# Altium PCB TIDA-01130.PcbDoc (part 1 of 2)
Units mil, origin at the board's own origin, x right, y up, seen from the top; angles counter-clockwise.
Board outline 1055.12 x 1877.5 mil, 6 copper layers (Layer 1 - Top Layer, Layer 2 - GND, Layer 3 - Signal, Layer 4 - Signal, Layer 5 - PWR, Layer 6 - Bottom Layer), stack 66.234 mil thick; 91 components, 54 nets, 295 pads, 113 vias.
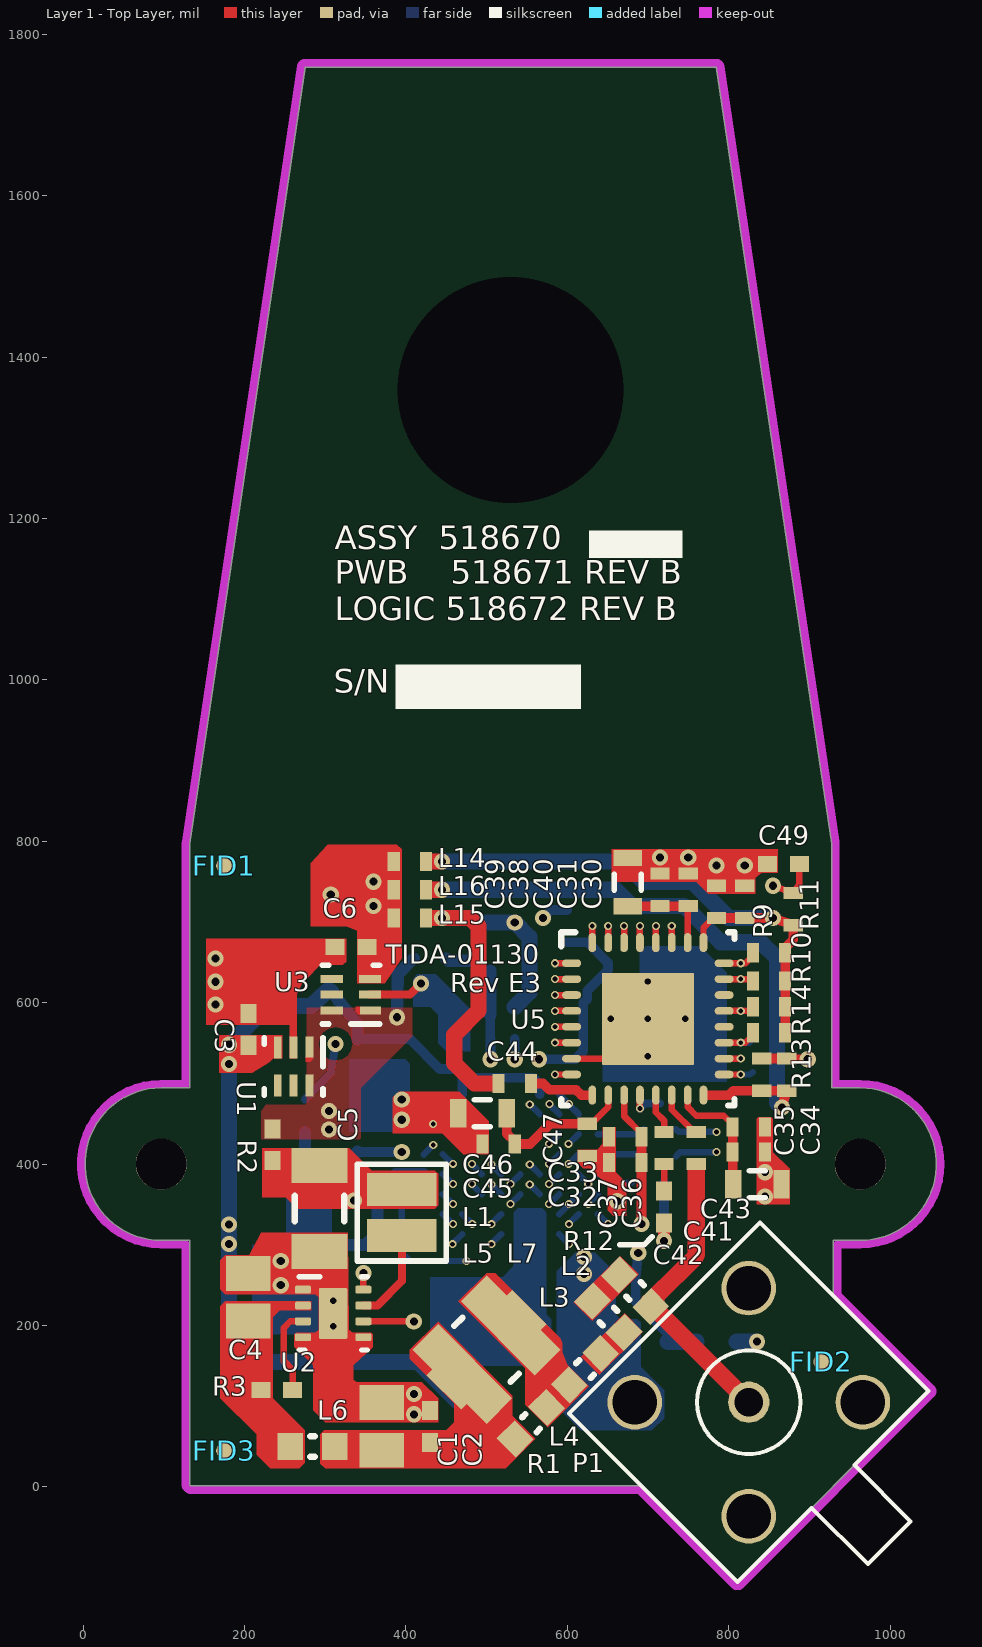
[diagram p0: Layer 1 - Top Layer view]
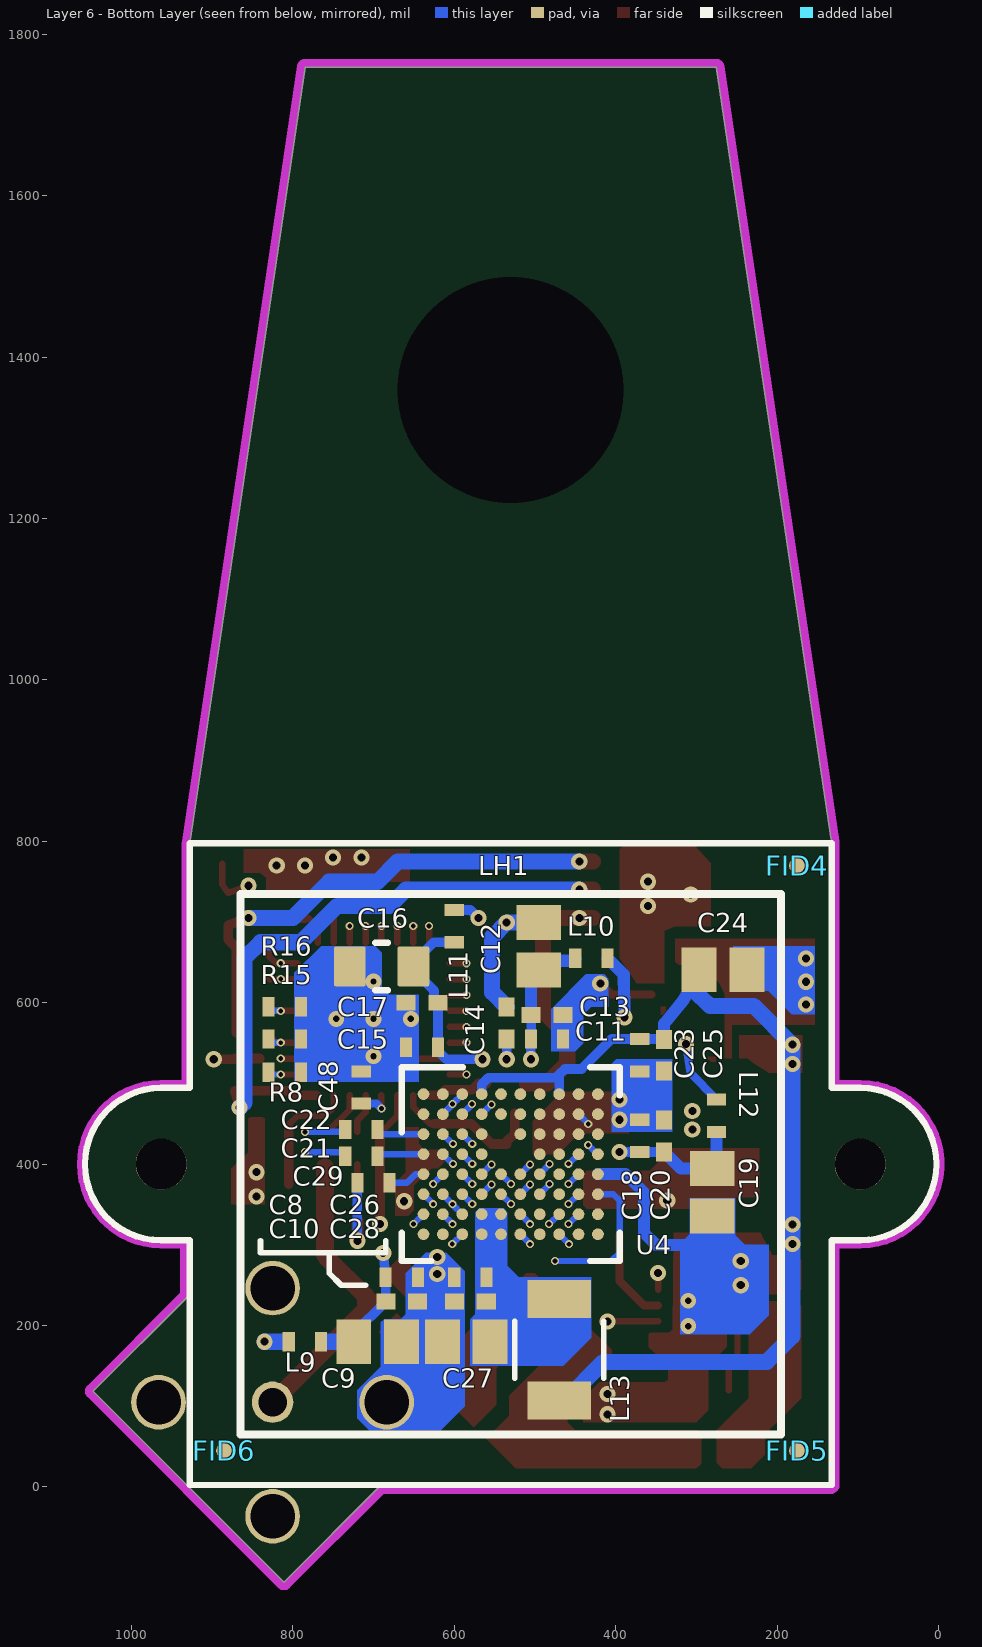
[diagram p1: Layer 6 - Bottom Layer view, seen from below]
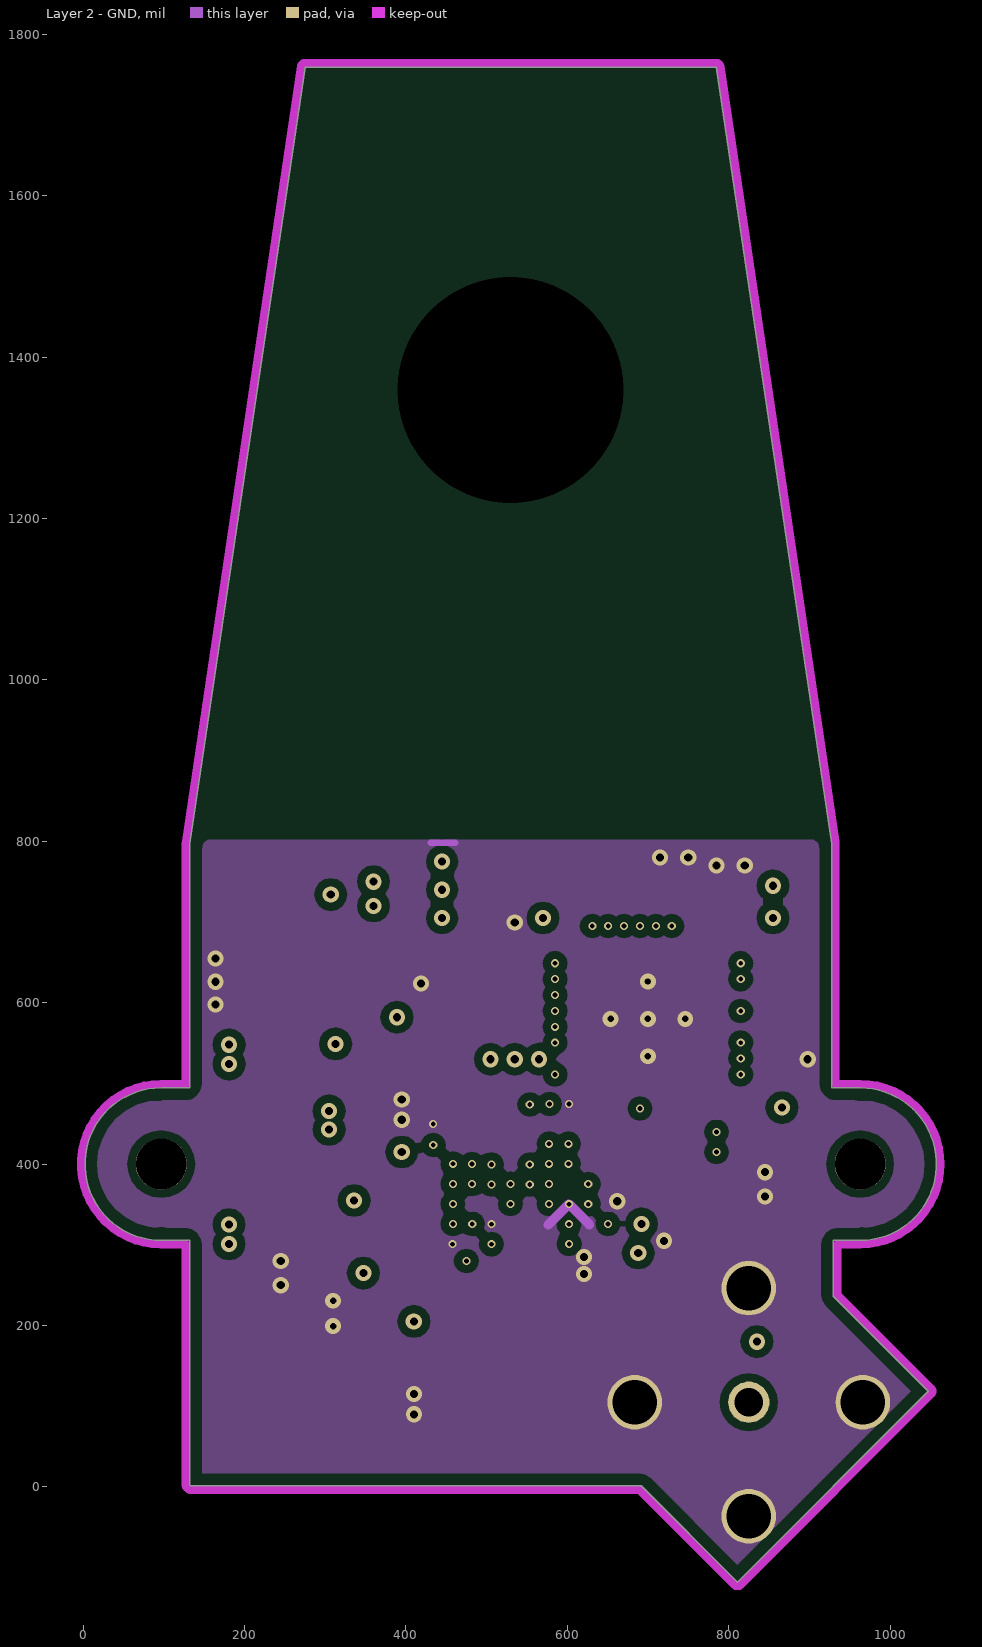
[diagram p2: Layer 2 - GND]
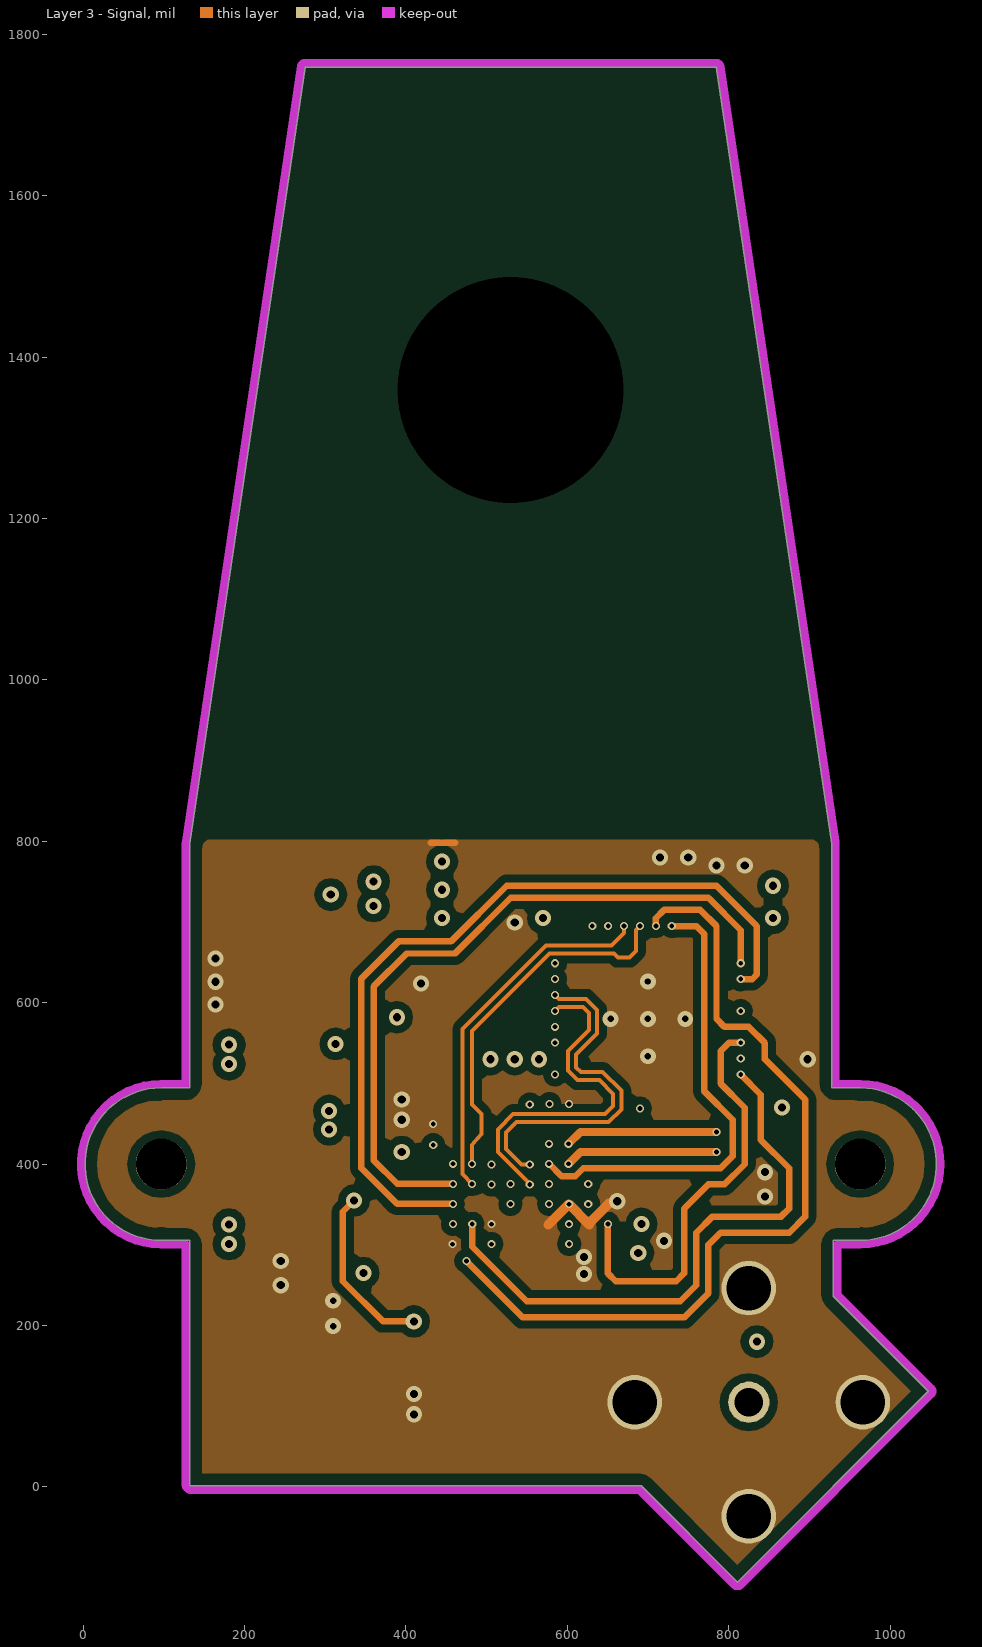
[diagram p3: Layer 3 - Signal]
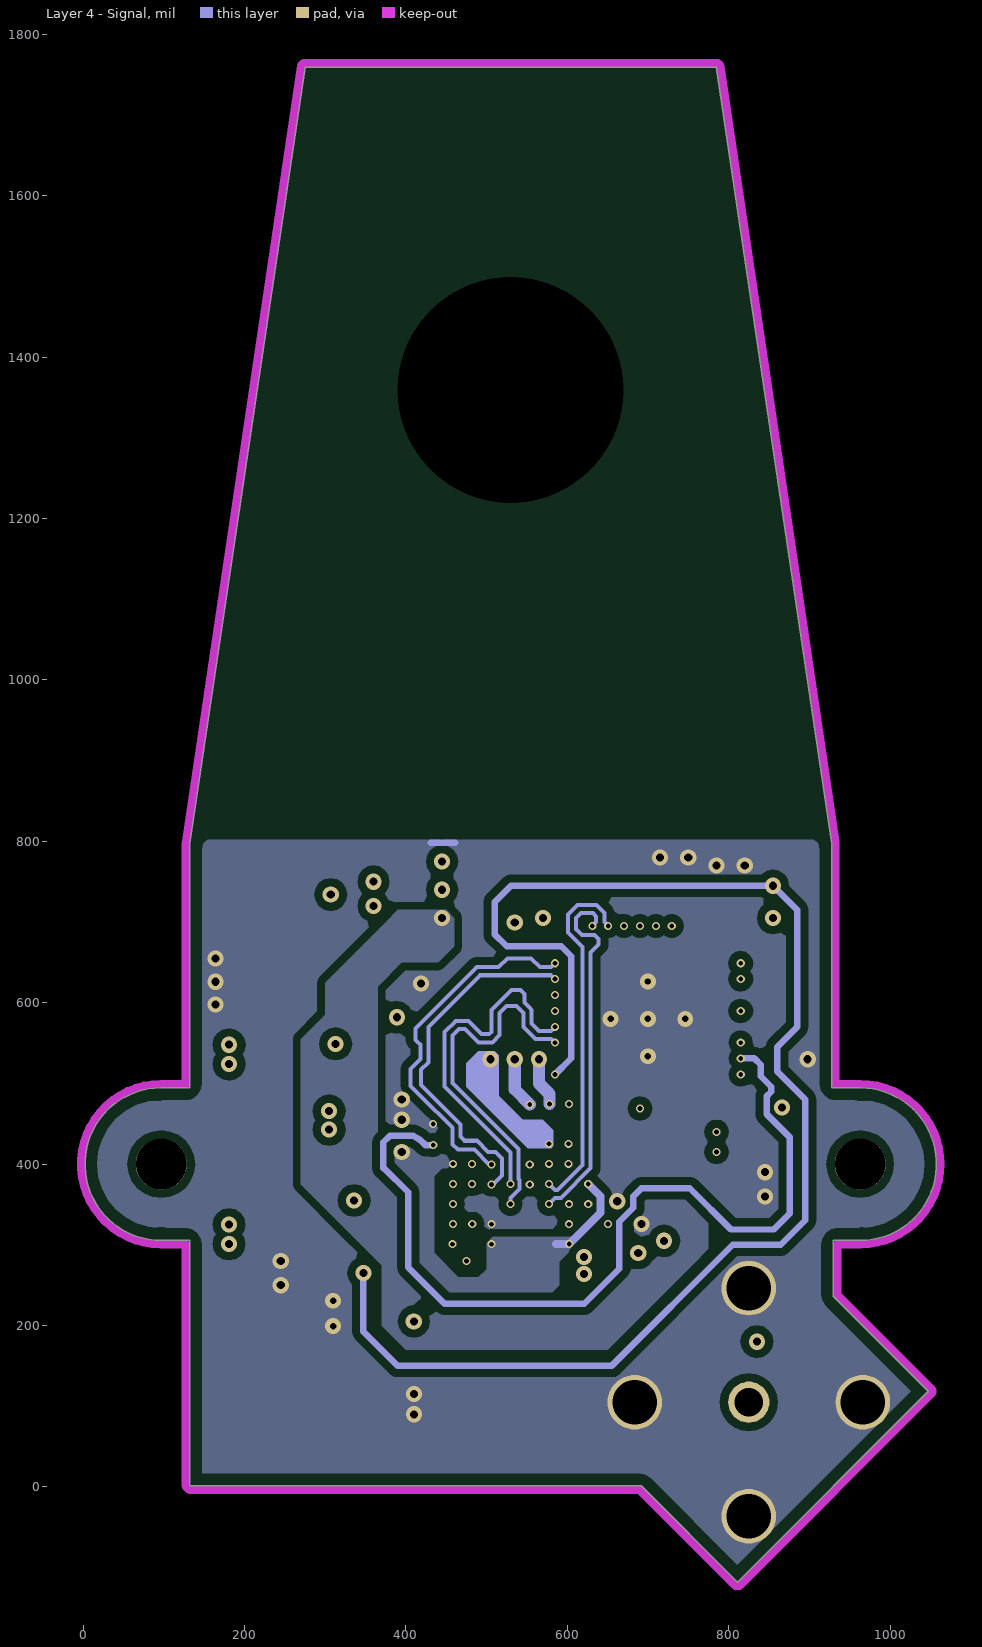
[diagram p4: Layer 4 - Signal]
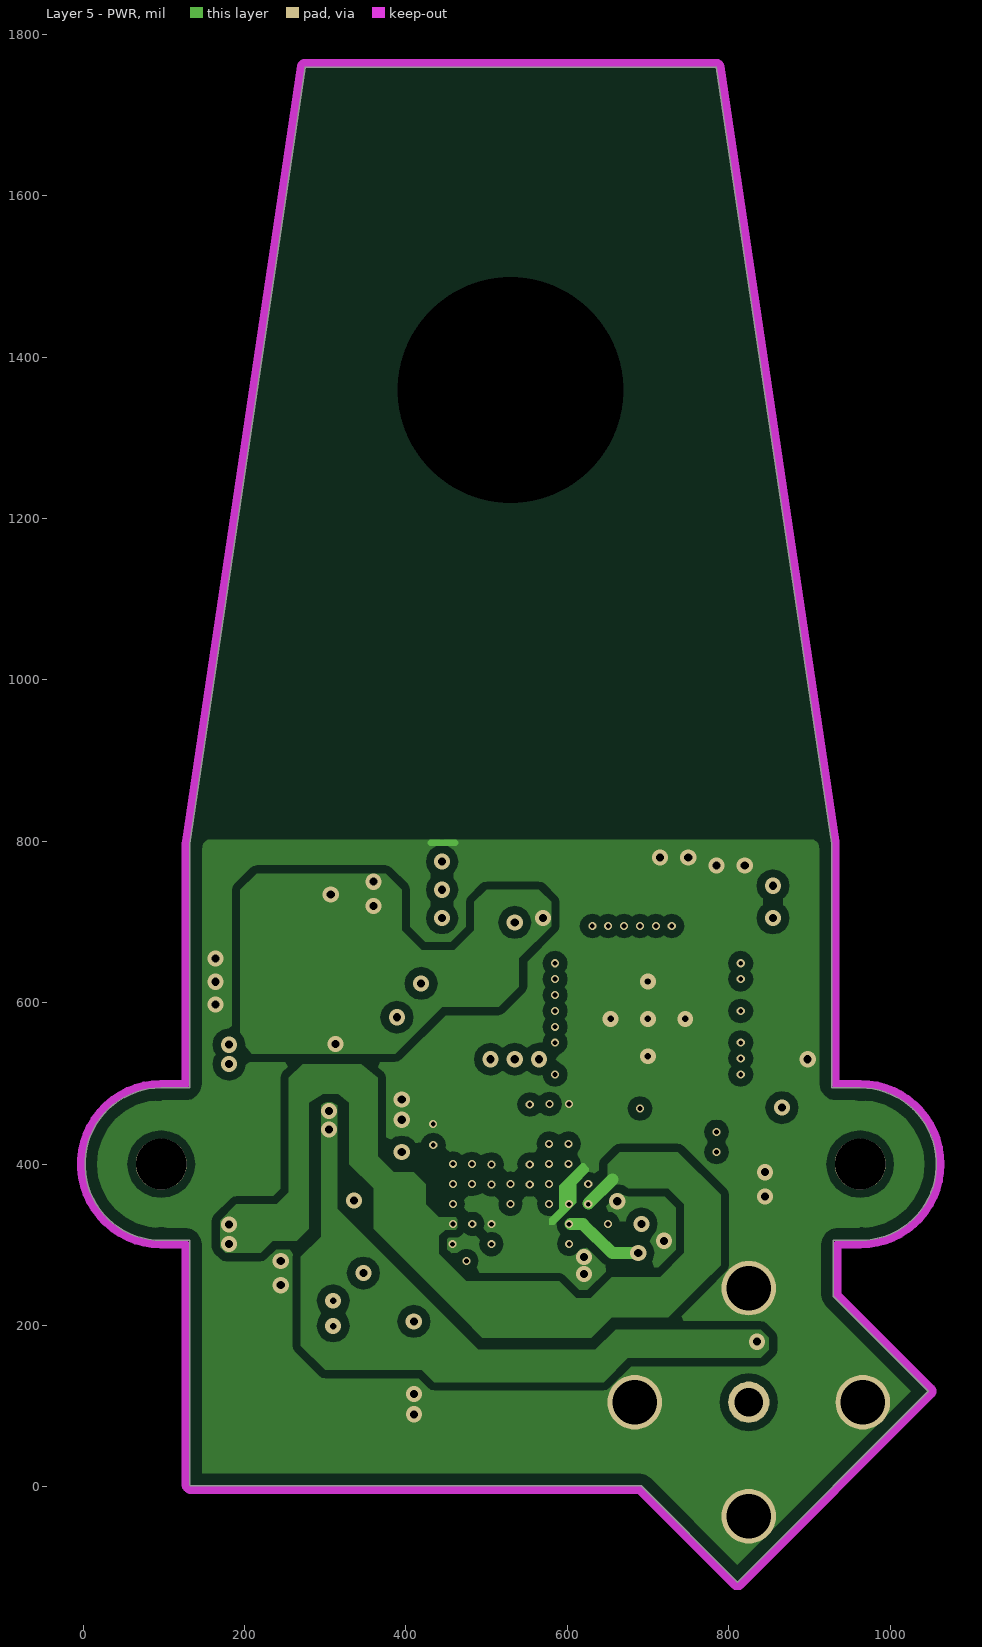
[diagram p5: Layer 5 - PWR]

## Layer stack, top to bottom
Top Solder: solder mask 0.4, Solder Resist, Dk 3.5
Layer 1 - Top Layer: signal copper 1.4
Dielectric 1: prepreg 12.6, 370HR, Dk 4.2
Layer 2 - GND: signal copper 1.4
Dielectric 2: core 8, 370HR, Dk 4.2
Layer 3 - Signal: signal copper 1.417
Dielectric 3: prepreg 16.6, 370HR, Dk 4.2
Layer 4 - Signal: signal copper 1.417
Dielectric 4: core 8, 370HR, Dk 4.2
Layer 5 - PWR: signal copper 1.4
Dielectric 5: prepreg 12.6, 370HR, Dk 4.2
Layer 6 - Bottom Layer: signal copper 1.4
Bottom Solder: solder mask 0.4, Solder Resist, Dk 3.5

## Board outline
96.93,305.51 132.36,305.51 132.36,2.36 133.35,1.37 691.63,1.37 811,-118 1047.5,118.5 929.63,236.37 929.63,305.51 963.07,305.51 ccw(c963.07,400) 963.07,494.49 927.64,494.49 927.64,797.64 927.64,797 784.75,1759.5 275.25,1759.5 132.36,797 132.36,797.64 132.36,494.49 96.93,494.49 ccw(c96.93,400)

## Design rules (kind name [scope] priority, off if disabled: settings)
AcuteAngle [All] p1 off: minimum=4.50000000000000E+0001 checktracksonly=FALSE
AssemblyTestPointUsage [All] p1: valid=2
Clearance Clearance_BoardEdge_MountingHoles [OnCopper and InComponentClass('Mounting Holes') vs IsKeepOut] p1 off: gap=30 ignorepadtopadclearanceinfootprint=FALSE except(0: Arc-Hole Track-Hole SMDPad-Hole THPad-Hole Via-Hole Fill-Hole Poly-Hole Region-Hole Text-Hole)
Clearance Clearance_BoardEdge_Poly [OnCopper and InPoly vs IsKeepOut] p2: gap=15 ignorepadtopadclearanceinfootprint=FALSE except(0: Arc-Hole Track-Hole SMDPad-Hole THPad-Hole Via-Hole Fill-Hole Poly-Hole Region-Hole Text-Hole)
Clearance Clearance_BoardEdge [OnCopper and Not InComponentClass('Logo') and not InComponentClass('FiducialMark') and not InRegion(1000,500,4000,800) and Not IsKeepout vs IsKeepOut and Not OnLayer('Keep-out Layer')] p3: gap=11 ignorepadtopadclearanceinfootprint=FALSE except(0: Arc-Hole Track-Hole SMDPad-Hole THPad-Hole Via-Hole Fill-Hole Poly-Hole Region-Hole Text-Hole)
Clearance Clearance_Poly [InPolygon] p4: gap=10 ignorepadtopadclearanceinfootprint=FALSE except(0: Arc-Hole Track-Hole SMDPad-Hole THPad-Hole Via-Hole Fill-Hole Poly-Hole Region-Hole Text-Hole)
Clearance [All] p5: gap=4 ignorepadtopadclearanceinfootprint=FALSE except(0: Arc-Hole Track-Hole SMDPad-Hole THPad-Hole Via-Hole Fill-Hole Poly-Hole Region-Hole Text-Hole)
ComponentClearance ComponentClearance_1 [issmtcomponent] p1: gap=0 collisioncheckmode=3 verticalgap=0 showdistances=FALSE
ComponentClearance ComponentClearance_Shunt [InComponentClass('Header') vs InComponentClass('Shunt')] p2: gap=0 collisioncheckmode=3 verticalgap=0 showdistances=FALSE
ComponentClearance ComponentClearance_Logo [InComponentClass('Logo')] p3: gap=0 collisioncheckmode=3 verticalgap=0 showdistances=FALSE
ComponentClearance ComponentClearance_ScrewToNut [(HasFootprint('NY PMS 440 0025 PH')) vs (HasFootprint('Keystone_1902C'))] p4: gap=5 collisioncheckmode=3 verticalgap=10 showdistances=FALSE
ComponentClearance ComponentClearance_MountingHoles [InComponentClass('Mounting Holes')] p5: gap=50 collisioncheckmode=3 verticalgap=50 showdistances=FALSE
ComponentClearance ComponentClearance_SmallPassives [HasFootprint('0201*') or HasFootprint('0402*') or HasFootprint('0508') or HasFootprint('0603*') or HasFootprint('0612') or HasFootprint('0805*') or HasFootprint('0815*') or HasFootprint('0830*') or HasFootprint('1206*') or HasFootprint('1210*') or HasFootprint('1808*') or HasFootprint('1812*') or HasFootprint('1825*') or HasFootprint('2010*') or HasFootprint('2220*') or HasFootprint('2225*') or HasFootprint('2512*') or HasFootprint('2728*') or HasFootprint('3518*') vs HasFootprint('0201*') or HasFootprint('0402*') or HasFootprint('0508') or HasFootprint('0603*') or HasFootprint('0612') or HasFootprint('0805*') or HasFootprint('0815*') or HasFootprint('0830*') or HasFootprint('1206*') or HasFootprint('1210*') or HasFootprint('1808*') or HasFootprint('1812*') or HasFootprint('1825*') or HasFootprint('2010*') or HasFootprint('2220*') or HasFootprint('2225*') or HasFootprint('2512*') or HasFootprint('2728*') or HasFootprint('3518*')] p6: gap=0 collisioncheckmode=3 verticalgap=0 showdistances=FALSE
ComponentClearance ComponentClearance_THtoSMT [IsThruComponent vs IsSMTComponent] p7: gap=0 collisioncheckmode=3 verticalgap=0 showdistances=FALSE
ComponentClearance ComponentClearance_THtoTH [IsThruComponent vs IsThruComponent] p8: gap=0 collisioncheckmode=3 verticalgap=0 showdistances=FALSE
ComponentClearance [All] p9: gap=0 collisioncheckmode=3 verticalgap=0 showdistances=FALSE
DiffPairsRouting DiffPair_Diff100_DiffPairsRouting [InDifferentialPairClass('Diff100')] p1: maxlimit=8 minlimit=5 mostfreqgap=8 toplayer_mingap=8 toplayer_minwidth=8 toplayer_maxwidth=8 toplayer_prefwidth=8 midlayer1_mingap=8 midlayer1_minwidth=8 midlayer1_maxwidth=8 midlayer1_prefwidth=8 midlayer2_mingap=8 midlayer2_minwidth=8 midlayer2_maxwidth=8 midlayer2_prefwidth=8 midlayer3_maxgap=5 midlayer3_prefgap=5 midlayer3_minwidth=5 midlayer3_maxwidth=5 midlayer3_prefwidth=5 midlayer4_maxgap=5 midlayer4_prefgap=5 midlayer4_minwidth=5 midlayer4_maxwidth=5 midlayer4_prefwidth=5 bottomlayer_mingap=8 bottomlayer_minwidth=8 bottomlayer_maxwidth=8 bottomlayer_prefwidth=8 maxuncoupledlength=500
DiffPairsRouting [All] p2: maxlimit=5 minlimit=5 mostfreqgap=5 toplayer_minwidth=5 toplayer_maxwidth=15 toplayer_prefwidth=8 midlayer1_minwidth=5 midlayer1_maxwidth=15 midlayer1_prefwidth=8 midlayer2_minwidth=5 midlayer2_maxwidth=15 midlayer2_prefwidth=8 midlayer3_minwidth=5 midlayer3_maxwidth=15 midlayer3_prefwidth=8 midlayer4_minwidth=5 midlayer4_maxwidth=15 midlayer4_prefwidth=8 bottomlayer_minwidth=5 bottomlayer_maxwidth=15 bottomlayer_prefwidth=8 maxuncoupledlength=1000
FabricationTestPointUsage TestPointUsage [All] p1: valid=2 allowmultiple=FALSE
FabricationTestpoint Testpoint [All] p1: side=3 testpointundercomponent=TRUE minsize=40 maxsize=100 preferedsize=60 minholesize=0 maxholesize=40 preferedholesize=32 testpointgrid=1 allowsidetop=TRUE allowsidebottom=TRUE usegrid=TRUE gridtolerance=0.01
FanoutControl Fanout_LCC [IsLCC] p1: bgadir=Out bgaviamode=Centered fanoutstyle=Auto fanoutdirection=Alternating viagrid=1 // Fanout_LCC (Default Rule)
FanoutControl Fanout_BGA [IsBGA] p2: bgadir=Out bgaviamode=Centered fanoutstyle=Auto fanoutdirection=Alternating viagrid=1 // Fanout_BGA (Default Rule)
FanoutControl Fanout_Default [All] p4: bgadir=Out bgaviamode=Centered fanoutstyle=Auto fanoutdirection=Alternating viagrid=1 // Fanout_Default (Default Rule)
FanoutControl Fanout_Small [(CompPinCount < 5)] p5: bgadir=Out bgaviamode=Centered fanoutstyle=Auto fanoutdirection=OutThenIn viagrid=1 // Fanout_Small (Default Rule)
HoleSize [All] p1: absolutevalues=TRUE maxlimit=280 minlimit=6 maxpercent=80.000 minpercent=20.000
MatchedLengths DiffPair_Diff100_MatchedLengths [InDifferentialPairClass('Diff100')] p1: tolerance=25 checknetsindiffpair=FALSE checkdiffpairvsdiffpair=TRUE checkxsignals=TRUE checkothers=TRUE
MinimumAnnularRing MinimumAnnularRing_ThermalPadVias [IsVia and InAnyComponent] p1: minimumring=5.91
MinimumAnnularRing [All] p2: minimumring=2
MinimumSolderMaskSliver MinimumSolderMaskSliver_Logo [InComponentClass('Logo') vs InComponentClass('Logo')] p1: minsoldermaskwidth=0.7
MinimumSolderMaskSliver [All] p2: minsoldermaskwidth=3.94
PlaneConnect [All] p1: planeconnectstyle=Relief reliefexpansion=10 reliefentries=4 reliefconductorwidth=10 reliefairgap=10
PolygonConnect [All] p1: connectstyle=Direct reliefconductorwidth=10 reliefentries=4 polygonreliefangle="90 Angle" airgapwidth=10
RoutingVias ThermalPadVias [IsVia and InAnyComponent] p1: holewidth=7.87 width=19.68 viastyle="Through Hole" minholewidth=7.87 minwidth=19.68 maxholewidth=12.99 maxwidth=23.62
RoutingVias [All] p2: holewidth=10 width=22 viastyle="Through Hole" minholewidth=6 minwidth=10 maxholewidth=40 maxwidth=65
SMDToCorner [All] p1: distance=25000
SilkToSilkClearance [All] p1: silktosilkclearance=0
SilkToSolderMaskClearance SilkscreenOverComponentPads [IsPad] p1: minsilkscreentomaskgap=0.2 clearancetoexposedcopper=TRUE
SolderMaskExpansion [All] p1: expansion=1
Width [All] p1: maxlimit=100 minlimit=5 preferedwidth=10 minimp=50.000000 maximp=50.000000 favimp=50.000000 checkconnectedcopper=TRUE
16 further rules are at their usual default settings.

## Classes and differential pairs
differential pair class Diff100: CSI0_CLK CSI0_D0 CSI0_D1 CSI0_D2 CSI0_D3
component class Serializer: C30 C31 C32 C33 C34 C35 C36 C37 C38 C39 C40 C41 C42 C43 C44 C45 C46 C47 C48 C49 L14 L15 L16 R9 R10 R11 R12 R13 R14 R15 R16 U5
component class "Coax Connection and Power Supply": C1 C2 C3 C4 C5 C6 L1 L2 L3 L4 L5 L6 L7 P1 R1 R2 R3 U1 U2 U3
component class Imager: C8 C9 C10 C11 C12 C13 C14 C15 C16 C17 C18 C19 C20 C21 C22 C23 C24 C25 C26 C27 C28 C29 L9 L10 L11 L12 L13 R8 R23 U4
component class AssemblyNote: ZZ1 ZZ2 ZZ3
component class FiducialMark: FID1 FID2 FID3 FID4 FID5 FID6
component class HDWR: FID1 FID2 FID3 FID4 FID5 FID6 LH1 ZZ1 ZZ2 ZZ3
differential pair CSI0_CLK: +CSI0_CLK_P -CSI0_CLK_N
differential pair CSI0_D0: +CSI0_D0_P -CSI0_D0_N
differential pair CSI0_D1: +CSI0_D1_P -CSI0_D1_N
differential pair CSI0_D2: +CSI0_D2_P -CSI0_D2_N
differential pair CSI0_D3: +CSI0_D3_P -CSI0_D3_N

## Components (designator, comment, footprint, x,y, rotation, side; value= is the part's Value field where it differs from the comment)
C1 "CGA4J1X7R1E475M125AC" 0805L 370,75 r90 top value=4.7µF
C2 "C1005X7R1E104K050BB" 0402L 430,75 r90 top value=0.1µF
C3 "CL05B105KQ5NQNC" 0402L 205,567 r90 top value=1.0µF
C4 "CL21B106KOQNNNE" 0805L 204.53,235 r90 top value=10uF
C5 "GRM31CR71A226KE15L" 1206L 293,345 r270 top value=22uF
C6 "CL05B105KQ5NQNC" 0402L 332,669 r180 top value=1.0µF
C8 "0402YC104KAT2A" 0402S 665,260 r180 bottom value=0.1uF
C9 "CL21B106KOQNNNE" 0805L 695,180 r180 bottom value=10uF
C10 "CL05B105KQ5NQNC" 0402L 665,230 r180 bottom value=1.0µF
C11 "0402YC104KAT2A" 0402S 485,555 r180 bottom value=0.1uF
C12 "CL21B106KOQNNNE" 0805L 495,670 r90 bottom value=10uF
C13 "CL05B105KQ5NQNC" 0402L 485,585 r180 bottom value=1.0µF
C14 "JMK105B7474KVHF" 0402L 535,575 r90 bottom value=0.47uF
C15 "0402YC104KAT2A" 0402S 640,545 r0 bottom value=0.1uF
C16 "CL21B106KOQNNNE" 0805_HV1 690,645 r0 bottom value=10uF
C17 "CL05B105KQ5NQNC" 0402L 640,600 r0 bottom value=1.0µF
C18 "0402YC104KAT2A" 0402S 370,435 r90 bottom value=0.1uF
C19 "CL21B106KOQNNNE" 0805L 280,365 r270 bottom value=10uF
C20 "CL05B105KQ5NQNC" 0402L 340,435 r90 bottom value=1.0µF
C21 "GRM155R71H103KA88D" 0402S 715,410 r180 bottom value=0.01uF
C22 "JMK105B7474KVHF" 0402S 715,443 r0 bottom value=0.47uF
C23 "0402YC104KAT2A" 0402S 370,535 r270 bottom value=0.1uF
C24 "CL21B106KOQNNNE" 0805L 267,641 r180 bottom value=10uF
C25 "CL05B105KQ5NQNC" 0402L 340,535 r270 bottom value=1.0µF
C26 "0402YC104KAT2A" 0402S 580,260 r0 bottom value=0.1uF
C27 "CL21B106KOQNNNE" 0805L 585,180 r0 bottom value=10uF
C28 "CL05B105KQ5NQNC" 0402L 580,230 r0 bottom value=1.0µF
C29 "JMK105B7474KVHF" 0402S 700,377 r0 bottom value=0.47uF
C30 "0402YC104KAT2A" 0402S 820,725 r90 top value=0.1uF
C31 "GRM155R71C103KA01D" 0402S 785,725 r90 top value=0.01uF
C32 "0402YC104KAT2A" 0402S 672,402 r180 top value=0.1uF
C33 "GRM155R71C103KA01D" 0402S 672,433.78 r180 top value=0.01uF
C34 "0402YC104KAT2A" 0402S 872,511 r90 top value=0.1uF
C35 "GRM155R71C103KA01D" 0402S 841,511 r90 top value=0.01uF
C36 "CGA2B3X7R1H333K050BB" 0402S 760,420 r90 top value=0.033uF
C37 "CGA2B3X7R1H153K050BB" 0402S 720,420 r90 top value=0.015uF
C38 "0402YC104KAT2A" 0402S 715,740 r90 top value=0.1uF
C39 "JMK107BB7475MA-T" 0603S 675,749.53 r270 top value=4.7uF
C40 "GRM155R71C103KA01D" 0402S 750,740 r90 top value=0.01uF
C41 "0402YC104KAT2A" 0402S 825,415 r0 top value=0.1uF
C42 "JMK107BB7475MA-T" 0603S 835.75,375 r180 top value=4.7uF
C43 "GRM155R71C103KA01D" 0402S 825,446 r0 top value=0.01uF
C44 "GRM155R70J223KA01D" 0402S 535,500 r0 top value=0.022uF
C45 "0402YC104KAT2A" 0402S 515,425 r180 top value=0.1uF
C46 "JMK107BB7475MA-T" 0603S 495,463 r0 top value=4.7uF
C47 "GRM155R71C103KA01D" 0402S 625,430 r270 top value=0.01uF
C48 "0402YC104KAT2A" 0402S 715,495 r90 bottom value=0.1uF
C49 "GRM155R60J474KE19D" 0402L 868,772 r180 top value=0.47uF
FID1 "Fiducial" Fiducial10-20#1 175,770 r0 top
FID2 "Fiducial" Fiducial10-20#2 885,45 r0 top
FID3 "Fiducial" Fiducial10-20#1 175,45 r0 top
FID4 "Fiducial" Fiducial10-20#1 175,770 r90 bottom
FID5 "Fiducial" Fiducial10-20#1 175,45 r90 bottom
FID6 "Fiducial" Fiducial10-20#1 885,45 r90 bottom
L1 "XPL2010-222MLB" XPL2010 395.04,340 r90 top value=2.2uH
L2 "BLM18HE152SN1D" 0603L 684,243 r135 top value="1500 ohm"
L3 "BLM18HE152SN1D" 0603L 651,211 r315 top value="1500 ohm"
L4 "BLM18HE152SN1D" 0603L 622,146 r225 top value="1500 ohm"
L5 "LQH3NPN100NG0" LQH3NP_G0 500,170 r45 top value=10uH
L6 "BLM18AG102SN1D" 0603L 284.57,50 r180 top value="1000 ohm"
L7 "ADL3225V-470M-2P" ADL3225V 500,170 r225 top value=47uH
L9 "BLM15AX102SN1D" 0402S 785,180 r180 bottom value="1000 ohm"
L10 "BLM15AX102SN1D" 0402S 430,655 r0 bottom value="1000 ohm"
L11 "BLM15AX102SN1D" 0402S 600,695 r270 bottom value="1000 ohm"
L12 "BLM15AX102SN1D" 0402S 275,460 r270 bottom value="1000 ohm"
L13 "NLCV32T-R22M-PFR" NLCV32 470,170 r90 bottom value=220nH
L14 "BLM15AX102SN1D" 0402S 405,775 r0 top value="1000 ohm"
L15 "BLM15AX102SN1D" 0402S 405,705 r0 top value="1000 ohm"
L16 "BLM15AX102SN1D" 0402S 405,740 r0 top value="1000 ohm"
LH1 "CMT821" CMT821 530,400 r180 bottom locked
P1 "59S10H-40ML5-Y" 59S10H-40ML5-Y 825,105 r315 top locked
R1 "CRCW06034K02FKEA" 0603L 555,79 r45 top value=4.02k
R2 "CRCW04020000Z0ED" 0402L 235,424 r270 top value=0
R3 "CRCW040210K0JNED" 0402L 240,120 r180 top value=10k
R8 "CRCW040210K0JNED" 0402S 810,514 r0 bottom value=10k
R9 "CRCW04023K30JNED" 0402S 850,662 r0 top value=3.3k
R10 "CRCW04023K30JNED" 0402S 850,627 r0 top value=3.3k
R11 "CRCW040210K0JNED" 0402S 880,716 r270 top value=10k
R12 "CRCW040249R9FKED" 0402L 720,347 r90 top value=49.9
R13 "CRCW040210K0JNED" 0402S 850,563 r0 top value=10k
R14 "CRCW040210K0JNED" 0402S 850,595 r0 top value=10k
R15 "CRCW0402402RFKED" 0402S 810,555 r0 bottom value=402
R16 "CRCW0402402RFKED" 0402S 810,595 r0 bottom value=402
U1 "TLV70213DSERQ1" DSE0006A 261,521 r270 top
U2 "TPS62172QDSGRQ1" DSG0008A 310,215 r0 top
U3 "TLV70218DSERQ1" DSE0006A 332,610 r180 top
U4 "OV02775-E77Y-1A-Z" aCSP-77 530,400 r180 bottom locked
U5 "DS90UB953QRHBQ1" RHB0032B 700,580 r0 top locked
ZZ1 "These assemblies are ESD sensitive, ESD precautions shall be observed." AssemblyNote 200,2100 r0 top
ZZ2 "These assemblies must be clean and free from flux and all contaminants. Use of no clean flux is not acceptable." AssemblyNote 200,2000 r0 top
ZZ3 "These assemblies must comply with workmanship standards IPC-A-610 Class 2, unless otherwise specified." AssemblyNote 200,1900 r0 top

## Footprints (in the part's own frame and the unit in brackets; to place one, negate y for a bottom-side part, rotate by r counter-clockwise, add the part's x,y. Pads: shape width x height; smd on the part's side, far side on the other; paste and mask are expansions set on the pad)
59S10H-40ML5-Y [mm] "Rosenberger Straight Plug"
  round 1.3 hole 0.9 mask+0: 1(0,0)
  round 1.72 hole 1.4 mask+0: 2(-2.54,2.54) 3(-2.54,-2.54) 4(2.54,-2.54) 5(2.54,2.54)
  silkscreen extent -3.75,-4.25 6.25,4.25
0402L [mm] "0402 from SM-752 data"
  rect 0.6x0.5 smd: 1(-0.5,0) 2(0.5,0)
  body extent -0.55,-0.3 0.55,0.3, height 0.6
0402S [mil] "Based on C0402S footprint from PADS legacy"
  rect 15x24 smd: 1(-20,0) 2(20,0)
  body extent -22,-12 22,12, height 24
0603L [mm] "0603 from SM-752 data"
  rect 0.8x0.85 smd: 1(-0.7,0) 2(0.7,0)
  silkscreen extent -0.07,-0.32 0.07,0.32, body extent -0.87,-0.47 0.87,0.47, height 1
0603S [mil]
  rect 20x35 smd: 1(-30,0) 2(30,0)
  silkscreen extent -10,-17 10,17, body extent -34,-19 34,19, height 39
0805_HV1 [mm] "Custom footprint based on analyzing multiple manufacturer recommendations"
  rrect10% 1x1.25 smd: 1(-1,0) 2(1,0)
  silkscreen extent -0.2,-0.75 0.2,0.75, body extent -1.1,-0.72 1.1,0.73, height 1.45
0805L [mm] "0805 from SM-752 data"
  rect 1.1x1.4 smd: 1(-0.75,0) 2(0.75,0)
  body extent -1.1,-0.72 1.1,0.72, height 1.1
1206L [mm] "1206 from SM-752 data"
  rect 1.1x1.75 smd: 1(-1.35,0) 2(1.35,0)
  silkscreen extent -0.4,-0.77 0.4,0.77, body extent -1.7,-0.9 1.7,0.9, height 1.35
aCSP-77 [mm] "BGA, 77-Leads, Body 6.534x5.724mm"
  round 0.37 smd: A1(-2.745,2.205) A2(-2.135,2.205) A3(-1.525,2.205) A4(-0.915,2.205) A5(-0.305,2.205) A6(0.305,2.205) A7(0.915,2.205) A8(1.525,2.205) A9(2.135,2.205) A10(2.745,2.205) B1(-2.745,1.575) B2(-2.135,1.575) B3(-1.525,1.575) B4(-0.915,1.575) B5(-0.305,1.575) B6(0.305,1.575) B7(0.915,1.575) B8(1.525,1.575) B9(2.135,1.575) B10(2.745,1.575) C1(-2.745,0.945) C2(-2.135,0.945) C3(-1.525,0.945) C4(-0.915,0.945) C6(0.305,0.945) C7(0.915,0.945) C8(1.525,0.945) C9(2.135,0.945) C10(2.745,0.945) D1(-2.745,0.315) D2(-2.135,0.315) D3(-1.525,0.315) D4(-0.915,0.315) D7(0.915,0.315) D8(1.525,0.315) D9(2.135,0.315) D10(2.745,0.315) E1(-2.745,-0.315) E2(-2.135,-0.315) E3(-1.525,-0.315) E4(-0.915,-0.315) E5(-0.305,-0.315) E6(0.305,-0.315) E7(0.915,-0.315) E8(1.525,-0.315) E9(2.135,-0.315) E10(2.745,-0.315) F1(-2.745,-0.945) F2(-2.135,-0.945) F3(-1.525,-0.945) F4(-0.915,-0.945) F5(-0.305,-0.945) F6(0.305,-0.945) F7(0.915,-0.945) F8(1.525,-0.945) F9(2.135,-0.945) F10(2.745,-0.945) G1(-2.745,-1.575) G2(-2.135,-1.575) G3(-1.525,-1.575) G4(-0.915,-1.575) G5(-0.305,-1.575) G6(0.305,-1.575) G7(0.915,-1.575) G8(1.525,-1.575) G9(2.135,-1.575) G10(2.745,-1.575) H1(-2.745,-2.205) H2(-2.135,-2.205) H3(-1.525,-2.205) H4(-0.915,-2.205) H5(-0.305,-2.205) H6(0.305,-2.205) H7(0.915,-2.205) H8(1.525,-2.205) H9(2.135,-2.205) H10(2.745,-2.205)
  silkscreen extent -3.43,-3.05 3.43,3.05, body extent -3.28,-2.88 3.28,2.88, height 1.04
ADL3225V [mm] "SMD, 2-Leads, Body 3.2x2.5mm"
  rect 0.9x1.53 smd: 1(-1.45,0) 2(1.45,0)
  silkscreen extent -0.18,-1.25 0.18,1.25, body extent -1.61,-1.25 1.61,1.25, height 2.4
AssemblyNote [mil] "Assembly Note"
CMT821 [mm] "SUNEX Lens Holder"
  round 1.6 hole 1.6 unplated paste+0: MT1(-11,0) MT2(11,0)
  M6 Assembly Bottom keep-out lines w0.2: 8.5,-8.5 8.5,8.5 -8.5,8.5 -8.5,-8.5 8.5,-8.5
  silkscreen extent -13.4,-10.1 13.4,10.1
DSE0006A [mm] "TI recommended land pattern"
  rect 0.66x0.25 smd: 1(-0.62,0.5)
  rect 0.7x0.25 smd: 2(-0.6,0) 3(-0.6,-0.5) 4(0.6,-0.5) 5(0.6,0) 6(0.6,0.5)
  Layer 1 - Top Layer region: -0.3,0.625 -0.25,0.625 -0.15,0.525 -0.15,0.375 -0.3,0.375
  silkscreen extent -0.9,-0.92 0.9,0.92, body extent -0.77,-0.77 0.77,0.77, height 0.8
DSG0008A [mm] "SON, 8-Leads, Body 2x2mm, Pitch 0.5mm, Thermal Pad 1.6x0.9mm, TI Recommended"
  rrect40% 0.5x0.25 smd: 1(-0.95,0.75) 2(-0.95,0.25) 3(-0.95,-0.25) 4(-0.95,-0.75) 5(0.95,-0.75) 6(0.95,-0.25) 7(0.95,0.25) 8(0.95,0.75)
  rrect11% 0.9x1.6 smd paste-0.45: 9(0,0)
  silkscreen extent -1.07,-1.15 1.07,1.15, body extent -1.05,-1.05 1.05,1.05, height 0.8
Fiducial10-20#1 [mil]
  round 20 smd paste-19.68 mask+19.68: 1(0,0)
Fiducial10-20#2 [mil]
  round 20 smd paste-19.68 mask+19.68: 1(30,110)
LQH3NP_G0 [mm] "MURATA"
  rect 1.15x3.3 smd: 1(-1.075,0) 2(1.075,0)
  body extent -1.6,-1.6 1.6,1.6, height 1.01
NLCV32 [mm] "TDK"
  rect 1.2x2 smd: 1(-1.6,0) 2(1.6,0)
  silkscreen extent -0.9,-1.4 0.9,1.4, body extent -1.7,-1.35 1.7,1.35, height 2.4
RHB0032B [mm] "QFN, 32-Leads, Body 5x5mm, Pitch 0.5mm, Thermal Pad 2.9x2.9mm"
  rrect100% 0.6x0.24 smd: 1(-2.4,1.75) 2(-2.4,1.25) 3(-2.4,0.75) 4(-2.4,0.25) 5(-2.4,-0.25) 6(-2.4,-0.75) 7(-2.4,-1.25) 8(-2.4,-1.75) 17(2.4,-1.75) 18(2.4,-1.25) 19(2.4,-0.75) 20(2.4,-0.25) 21(2.4,0.25) 22(2.4,0.75) 23(2.4,1.25) 24(2.4,1.75)
  rrect100% 0.24x0.6 smd: 9(-1.75,-2.4) 10(-1.25,-2.4) 11(-0.75,-2.4) 12(-0.25,-2.4) 13(0.25,-2.4) 14(0.75,-2.4) 15(1.25,-2.4) 16(1.75,-2.4) 25(1.75,2.4) 26(1.25,2.4) 27(0.75,2.4) 28(0.25,2.4) 29(-0.25,2.4) 30(-0.75,2.4) 31(-1.25,2.4) 32(-1.75,2.4)
  rrect3% 2.9x2.9 smd paste-1.725: 33(0,0)
  silkscreen extent -2.72,-2.73 2.72,2.72, body extent -2.57,-2.58 2.58,2.57, height 1.01
XPL2010 [mm] "Coilcraft recommended land pattern Document 646-2 Revised 3/28/11"
  rect 1.04x2.2 smd: 1(-0.725,0) 2(0.725,0)
  silkscreen extent -1.52,-1.4 1.52,1.4, body extent -1.05,-1.1 1.05,1.1, height 1

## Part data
C1: library part C2012X7R1E474K, "CAP, CERM, 4.7uF, 25V, +/-20%, X7R, 0805", Manufacturer="TDK Corporation", Operating Temperature="-55°C ~ 125°C", Ratings=AEC-Q200, Supplier Part Number 1=445-12761-1-ND, TempCo=X7R, Tolerance_%=±20%
C2: library part C1005X7R1E103K, "CAP, CERM, 0.1uF, 25V, +/-10%, X7R, 0402", Manufacturer="TDK Corporation", Operating Temperature="-55°C ~ 125°C", Ratings=-, Supplier Part Number 1=445-7348-1-ND, TempCo=X7R, Tolerance_%=±10%
C3 C6 C10 C13 C17 C20 C25 C28: library part Capacitor, "CAP CER 1UF 6.3V 10% X7R 0402", Alternate Manufacturer=-, Manufacturer="Samsung Electro-Mechanics America, Inc", Operating Temperature="-55°C ~ 125°C", Supplier Part Number 1=1276-1513-1-ND, TempCo=X7R, Tolerance_%=±10%
C4 C9 C12 C16 C19 C24 C27: "CAP, CERM, 10 µF, 16 V, +/- 10%, X7R, 0805", Cap_Case=0805, Manufacturer="Samsung Electro-Mechanics", TempCo=X7R, Tolerance_%=10, Value1=Unknown, Value2=16V, ValueDisplayed=10µF
C5: "CAP, CERM, 22uF, 10V, +/-10%, X7R, 1206", Cap_Case=1206, Manufacturer=MuRata, Supplier Part Number 1=490-5309-1-ND, TempCo=X7R, Tolerance_%=10, Value1=Unknown, Value2=10V, ValueDisplayed=22µF
C8 C11 C15 C18 C23 C26 C30 C32 C34 C38 C41 C45 C48: "CAP, CERM, 0.1 µF, 16 V, +/- 10%, X7R, 0402", Cap_Case=0402, Manufacturer=AVX, Supplier Part Number 1=478-7888-1-ND, TempCo=X7R, Tolerance_%=10, Value1=Unknown, Value2=16V, ValueDisplayed=0.1µF
C14 C22 C29: "CAP, CERM, 0.47 µF, 6.3 V, +/- 10%, X7R, 0402", Cap_Case=0402, Manufacturer="Taiyo Yuden", Supplier Part Number 1=587-3765-1-ND, TempCo=X7R, Tolerance_%=10, Value1=Unknown, Value2=6.3V, ValueDisplayed=0.47µF
C21: "CAP, CERM, 0.01 µF, 50 V, +/- 10%, X7R, 0402", Cap_Case=0402, Manufacturer=MuRata, Supplier Part Number 1=490-4516-1-ND, TempCo=X7R, Tolerance_%=10, Value1=Unknown, Value2=50V, ValueDisplayed=0.01µF
C31 C33 C35 C40 C43 C47: "CAP, CERM, 0.01uF, 16V, +/-10%, X7R, 0402", Cap_Case=0402, Manufacturer=MuRata, Supplier Part Number 1=490-1313-1-ND, TempCo=X7R, Tolerance_%=10, Value1=Unknown, Value2=16V, ValueDisplayed=0.01µF
C36: "CAP, CERM, 0.033 µF, 50 V, +/- 10%, X7R, 0402", Cap_Case=0402, Manufacturer=TDK, Supplier Part Number 1=445-6896-1-ND, TempCo=X7R, Tolerance_%=10, Value1=Unknown, Value2=50V, ValueDisplayed=0.033µF
C37: "CAP, CERM, 0.015 µF, 50 V, +/- 10%, X7R, AEC-Q200 Grade 1, 0402", Cap_Case=0402, Manufacturer=TDK, Supplier Part Number 1=445-6894-1-ND, TempCo=X7R, Tolerance_%=10, Value1="0.2162 ohm", Value2=50V, ValueDisplayed=0.015µF
C39 C42 C46: "CAP, CERM, 4.7 µF, 6.3 V, +/- 10%, X7R, 0603", Cap_Case=0603, Manufacturer="Taiyo Yuden", TempCo=X7R, Tolerance_%=10, Value1=Unknown, Value2=6.3V, ValueDisplayed=4.7µF
C44: "CAP, CERM, 0.022 µF, 6.3 V, +/- 10%, X7R, 0402", Cap_Case=0402, Manufacturer=MuRata, Supplier Part Number 1=GRM155R70J223KA01D-ND, TempCo=X7R, Tolerance_%=10, Value1=Unknown, Value2=6.3V, ValueDisplayed=0.022µF
C49: "CAP, CERM, 0.47 µF, 6.3 V, +/- 10%, X5R, 0402", Cap_Case=0402, Manufacturer=MuRata, Supplier Part Number 1=490-3266-1-ND, TempCo=X5R, Tolerance_%=10, Value1=Unknown, Value2=6.3V, ValueDisplayed=0.47µF
FID1 FID2 FID3 FID4 FID5 FID6: "Fiducial mark.  There is nothing to buy or mount.", Manufacturer=N/A
L1: "Inductor, Shielded, Composite, 2.2 µH, 1.3 A, 0.16 ohm, SMD", Manufacturer=Coilcraft, Value1="0.16 ohm", Value2=1.3A, ValueDisplayed=2.2µH
L2 L3 L4: "Ferrite Bead, 1500 ohm @ 100 MHz, 0.5 A, 0603", Manufacturer=MuRata, Supplier Part Number 1=490-5216-1-ND, Value1="0.5 ohm", Value2=0.5A
L5: "Inductor, Wirewound, Ferrite, 10 µH, 0.5 A, 0.57 ohm, SMD", Manufacturer=MuRata, Supplier Part Number 1=490-5123-1-ND, Value1="0.57 ohm", Value2=0.5A, ValueDisplayed=10µH
L6: "Ferrite Bead, 1000 ohm @ 100 MHz, 0.4 A, 0603", Manufacturer=MuRata, Supplier Part Number 1=490-1015-1-ND, Value1="0.5 ohm", Value2=0.4A
L7: "Inductor, Wirewound, 47 µH, 0.35 A, 1.3 ohm, SMD", Manufacturer=TDK, Value1="1.3 ohm", Value2=0.35A, ValueDisplayed=47µH
L9 L10 L11 L12 L14 L15 L16: "Ferrite Bead, 1000 ohm @ 100 MHz, 0.35 A, 0402", Manufacturer=MuRata, Supplier Part Number 1=490-5442-1-ND, Value1="0.49 ohm", Value2=0.35A
L13: "Inductor, Wirewound, Ferrite, 220 nH, 2.4 A, 0.027 ohm, SMD", Manufacturer=TDK, Supplier Part Number 1=445-3644-1-ND, Value1="0.027 ohm", Value2=2.4A, ValueDisplayed=220nH
LH1: "Sunex Lens Holder", Manufacturer="Sunex Inc."
P1: "Straight Plug PCB", Alternate Manufacturer=-, Manufacturer=Rosenberger
R1: "RES, 4.02 k, 1%, 0.1 W, 0603", Manufacturer=Vishay-Dale, Power_W=0.1, Supplier Part Number 1=541-4.02KHCT-ND, TempCo="100 ppm/C", Tolerance_%=1, Value1=1%, Value2=0.1W, Value_Code=4k02, ValueDisplayed=4.02k
R2: "RES, 0 ohm, 5%, 0.063W, 0402", Manufacturer=Vishay-Dale, Power_W=0.063, Supplier Part Number 1=541-0.0JCT-ND, TempCo="200 ppm/C", Tolerance_%=5, Value1=5%, Value2=0.063W, Value_Code=0000
R3 R8 R11 R13 R14: "RES, 10k ohm, 5%, 0.063W, 0402", Manufacturer=Vishay-Dale, Power_W=0.063, Supplier Part Number 1=71-CRCW0402J-10K-E3, TempCo="200 ppm/C", Tolerance_%=5, Value1=5%, Value2=0.063W, Value_Code=10k0
R9 R10: "RES, 3.3 k, 5%, 0.063 W, 0402", Manufacturer=Vishay-Dale, Power_W=0.063, Supplier Part Number 1=541-3.3KJCT-ND, TempCo="200 ppm/C", Tolerance_%=5, Value1=5%, Value2=0.063W, Value_Code=3k30, ValueDisplayed=3.3k
R12: "RES, 49.9 ohm, 1%, 0.063W, 0402", Manufacturer=Vishay-Dale, Power_W=0.063, Supplier Part Number 1=541-49.9LCT-ND, TempCo="100 ppm/C", Tolerance_%=1, Value1=1%, Value2=0.063W, Value_Code=49R9
R15 R16: "RES, 402, 1%, 0.063 W, 0402", Manufacturer=Vishay-Dale, Power_W=0.063, Supplier Part Number 1=541-402LCT-ND, TempCo="100 ppm/C", Tolerance_%=1, Value1=1%, Value2=0.063W, Value_Code=402R, ValueDisplayed=402
U1 U3: "Automotive 300mA, Low IQ, Low-Dropout Regulator, DSE0006A (WSON-6)", Alternate Manufacturer="Texas Instruments"
U2: "3-V to17-V 0.5-A Step-Down Converters with DCS-Control™, DSG0008A (WSON-8)", Alternate Manufacturer="Texas Instruments", Alternate PartNumber=TPS62172QDSGTQ1
U4: "Color CMOS 1080p (1920x1080) high dynamicrange(HDR) high definition image sensor, aCSP-77", Manufacturer="OmniVision Technologies"
U5: "FPD-Link III SerDes with CSI-2 interfaces for 2.3MP/60fps camera, RHB0032B", Alternate Manufacturer="Texas Instruments"
ZZ1 ZZ2 ZZ3: library part AssemblyNote, Alternate Manufacturer=-

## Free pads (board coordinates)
  round 60 hole 280 unplated: 0(530,1359.5)

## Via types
v1: diameter 10, hole 6, Layer 1 - Top Layer to Layer 6 - Bottom Layer, tented both sides, 56 vias
v2: diameter 20, hole 10, Layer 1 - Top Layer to Layer 6 - Bottom Layer, tented both sides, 50 vias
v3: diameter 19.68, hole 7.87, Layer 1 - Top Layer to Layer 6 - Bottom Layer, tented both sides, 7 vias

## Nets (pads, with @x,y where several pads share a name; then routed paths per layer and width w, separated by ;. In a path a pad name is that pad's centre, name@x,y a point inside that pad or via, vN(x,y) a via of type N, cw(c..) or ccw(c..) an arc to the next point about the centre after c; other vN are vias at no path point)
1V3: C3.1 C23.1 C24.1 C25.1 L13.1 U1.3 U4.A4 U4.A8 U4.F1 U4.G9 | length 1273.3
  Layer 5 - PWR w15: v1@626.39,351.39 656,381
  Layer 6 - Bottom Layer w8: U4.G9@445.94,337.99 457.95,325.98 v1(458.35,325.98) ; v1(626.06,350.39) 626.06,350.79 U4.F1@638.07,362.8
  Layer 6 - Bottom Layer w12: C25.1@340,554.68 340.32,555 C23.1@370,555 405,555 442,518 463,518 469.96,511.04 ; U4.A8@469.96,486.81 469.96,511.04 ; U4.A4@566.02,486.81 566.02,498.98 558,507 474,507 469.96,511.04
  Layer 6 - Bottom Layer w15: C24.1@309,616 317,602 340,574 C25.1@340,554.68
  Layer 6 - Bottom Layer w20: C24.1@304,616 283,596 229,596 v2(181,548) v2(181,524) 181,400.32 180.91,359.09 v2(180.91,325) 180.91,186.73 212.64,155 415,155 462.99,107.01 L13.1@470,107.01 L13.1@475,107.01
  other v2: 180.91,301
1V8: C6.1 L11.1 L12.1 L14.1 L15.1 L16.1 U3.3 | length 116.6
  Layer 6 - Bottom Layer w10: L12.1@275,480 307,513 v2(313,549)
  Layer 6 - Bottom Layer w12: v2(570,705) 580,715 L11.1@600,715
  other v2: 360,720 307,734 360,750
3V3: L9.1 L10.1 R2.1 U1.1 U1.6 U3.1 U3.6 | length 106.3
  Layer 6 - Bottom Layer w15: v2(389,582) 390,635 L10.1@410,655
  Layer 6 - Bottom Layer w20: L9.1@810,180 v2(835,180)
  other v2: 305,443 305,466
3V3_PG: C49.1 R11.1 U2.8 U5.8 | length 1924.4
  Layer 1 - Top Layer w8: U2.8@347.4,244.53 v2(347.4,265) ; v1(585,511.1) U5.8@605.51,511.1 ; v2(855,745) R11.1@880,736 887.68,746.85 C49.1@887.68,772
  Layer 4 - Signal w8: v2(347.4,265) 347.4,192.6 390,150 655,150 805,300 864.65,300 895,330.35 895,480 860,515 860,545 885,570 885,715 v2(855,745) 530.35,745 510,724.65 510,685 525,670 592.44,670 605,657.44 605,531.1 v1(585,511.1)
AVDD: C15.1 C16.1 C17.1 L11.2 U4.B3 | length 320.8
  Layer 4 - Signal w15: v2(565,530) 565,500 578.03,486.97 v1(578.03,474.41)
  Layer 6 - Bottom Layer w8: v1(578.03,474.41) 578.03,474.02 U4.B3@590.04,462.01
  Layer 6 - Bottom Layer w12: v2(565,530) 610,530 620,540 C15.1@620,545 620,599.68 C17.1@620.32,600 625,604.68 625,615 650.63,640.63 C16.1@650.63,645 650.63,649.37 625,675 L11.2@600,675
AVDD_LO: C14.1 U4.B4 | length 106.4
  Layer 4 - Signal w15: v2(535,530) 535,492.64 v1(553.62,474.02)
  Layer 6 - Bottom Layer w8: v1(553.62,474.02) 554.02,474.02 U4.B4@566.02,462.01
  Layer 6 - Bottom Layer w12: v2(535,530) C14.1@535,555.32
CSI0_CLK_N: U4.F5 U5.6 | length 486.8
  Layer 1 - Top Layer w8: v1(585,550.47) U5.6@605.51,550.47
  Layer 4 - Signal w5: v1(529.61,350.79) 529.61,357.83 541.11,369.33 541.11,380.35 539.61,381.85 539.61,418.54 457.76,500.39 457.76,559.37 466.03,567.64 473.36,567.64 475.14,565.86 475.14,565.72 489.86,551 507.14,551 516,559.86 516,587 525,596 537,596 546,587 546,569.86 560.6,555.26 580.21,555.26 v1(585,550.47)
  Layer 6 - Bottom Layer w8: v1(529.61,350.79) 530,350.79 U4.F5@542.01,362.8
CSI0_CLK_P: U4.E5 U5.5 | length 485.9
  Layer 1 - Top Layer w8: v1(585,570.16) U5.5@605.51,570.16
  Layer 4 - Signal w5: v1(529.61,375.59) 529.61,414.39 447.76,496.24 447.76,563.51 461.89,577.64 477.5,577.64 485.14,570 485.14,569.86 494,561 503,561 506,564 506,591.14 530.86,616 542,616 547,611 547,600.14 554.57,592.57 ; 556,591.14 556,574 564.74,565.26 580.1,565.26 v1(585,570.16)
  Layer 6 - Bottom Layer w8: v1(529.61,375.59) 530,375.59 U4.E5@542.01,387.6
CSI0_D0_N: U4.F4 U5.4 | length 489.6
  Layer 1 - Top Layer w8: v1(585,589.84) U5.4@605.51,589.84
  Layer 3 - Signal w5: v1(553.62,374.8) 553.62,375.24 514,414.86 514,443.14 532.86,462 647,462 657,472 657,486.86 639.86,504 612.86,504 601,515.86 601,540 627,566 627,587 619.32,594.68 589.84,594.68 v1(585,589.84)
  Layer 6 - Bottom Layer w8: v1(553.62,374.8) 554.02,374.8 U4.F4@566.02,362.8
CSI0_D0_P: U4.E4 U5.3 | length 483.2
  Layer 1 - Top Layer w8: v1(585,609.53) U5.3@605.51,609.53
  Layer 3 - Signal w5: v1(553.62,399.61) 543.39,399.61 524,419 524,439 537,452 651.14,452 667,467.86 667,491 644,514 617,514 611,520 611,535.86 634.07,558.93 637,561.86 637,591.14 634.07,594.07 623.46,604.68 589.84,604.68 v1(585,609.53)
  Layer 6 - Bottom Layer w8: v1(553.62,399.61) 554.02,399.61 U4.E4@566.02,387.6
CSI0_D1_N: U4.F6 U5.2 | length 481.9
  Layer 1 - Top Layer w8: v1(585,629.21) U5.2@605.51,629.21
  Layer 4 - Signal w5: v1@507.8,374.8 519,386 519,407 511,415 502,415 488,429 473,429 468,434 468,449 419,498 419,517 428,526 428,570 492.06,634.06 580,634.06 ; 580.16,634.06 v1(585,629.21)
  Layer 6 - Bottom Layer w8: v1(505.98,374.8) U4.F6@517.99,362.8
CSI0_D1_P: U4.E6 U5.1 | length 484
  Layer 1 - Top Layer w8: v1(585,648.9) U5.1@605.51,648.9
  Layer 4 - Signal w5: v1(505.98,399.61) 503.25,399.61 484.93,417.93 464.43,417.93 457.76,424.6 457.76,445.1 418.93,483.93 406,496.86 406,518.14 418,530.14 418,548 415,551 412.07,553.93 412.07,568.21 418.93,575.07 487.91,644.06 515.06,644.06 526,655 555.06,655 566,644.06 580.16,644.06 v1(585,648.9)
  Layer 6 - Bottom Layer w8: v1(505.98,399.61) U4.E6@517.99,387.6
CSI0_D2_N: U4.F3 U5.32 | length 485.6
  Layer 1 - Top Layer w8: U5.32@631.1,674.49 v1(631.1,695)
  Layer 4 - Signal w5: v1(577.64,350.79) 585.04,358.19 592.14,358.19 629,395.05 629,662 639,672 639,679 633.93,684.07 618.07,684.07 611.07,691.07 611.07,705.07 617,711 632,711 635.94,707.06 635.94,699.84 v1(631.1,695)
  Layer 6 - Bottom Layer w8: v1(577.64,350.79) 578.03,350.79 U4.F3@590.04,362.8
CSI0_D2_P: U4.E3 U5.31 | length 484.6
  Layer 1 - Top Layer w8: U5.31@650.79,674.49 v1(650.79,695)
  Layer 4 - Signal w5: v1(577.64,375.59) 585.04,368.19 588,368.19 619,399.19 619,669 604,684 601.07,686.93 601.07,709.21 612.86,721 636.14,721 645.94,711.2 645.94,699.84 v1(650.79,695)
  Layer 6 - Bottom Layer w8: v1(577.64,375.59) 578.03,375.59 U4.E3@590.04,387.6
CSI0_D3_N: U4.F7 U5.30 | length 494.5
  Layer 1 - Top Layer w8: U5.30@670.47,674.49 v1(670.47,695)
  Layer 3 - Signal w5: v1(481.97,375.59) 470,387.56 470,410 470.5,567.64 573.86,671 654.75,671 670.47,686.72 v1(670.47,695)
  Layer 6 - Bottom Layer w8: v1@481.57,375.59 481.18,375.59 v1@481.56,375.2 ; v1@482.18,374.56 v1@481.56,375.2 ; U4.F7@493.98,362.8 v1@481.57,375.2
CSI0_D3_P: U4.E7 U5.29 | length 494
  Layer 1 - Top Layer w8: U5.29@690.16,674.49 v1(690.16,695)
  Layer 3 - Signal w5: v1(482,400) 482,424 493.98,437.2 493.98,462.02 482,474 482,565 578,661 657.85,661 662.85,656 677,656 685.26,664.26 685.26,690.1 v1(690.16,695)
  Layer 6 - Bottom Layer w8: v1@482.39,400 v1(482,400) U4.E7@493.98,387.6
DOUTP_F: C36.1 L2.1 P1.1 | length 369.9
  Layer 1 - Top Layer w20: L2.1@707,228 L2.1@710.08,231.08
  Layer 1 - Top Layer w22: L2.1@701,229 P1.1@825,105 ; L2.1@709,222 710,237 758,284 ; 760,288 C36.1@760,396
DOVDD: C18.1 C19.1 C20.1 L12.2 U4.D9 U4.E2 U4.H3 U4.H6 | length 353.3
  Layer 4 - Signal w10: 586.18,301.18 v1(602.44,301.18) 641.06,339.8 641.06,360.2 v1(626.06,375.2)
  Layer 6 - Bottom Layer w8: U4.D9@445.94,412.4 457.95,400.39 v1(458.35,400.39) ; v1(505.98,300.79) 505.98,301.18 U4.H6@517.99,313.19 ; U4.H3@590.04,313.19 602.05,301.18 v1(602.44,301.18) ; U4.E2@614.06,387.6 626.06,375.59 v1(626.06,375.2)
  Layer 6 - Bottom Layer w12: C20.1@340,415.32 340.32,415 C18.1@370,415 v2(395,415)
  Layer 6 - Bottom Layer w15: L12.2@275,440 275,399.53 C19.1@280,394.53 319.21,394.53 C20.1@340,415.32
EVDD: C26.1 C27.1 C28.1 L13.2 U4.G4 U4.G5 U4.H4 U4.H5
FSIN: U4.D10 U5.18 | length 1128.6
  Layer 1 - Top Layer w8: U5.18@794.49,530.79 v1@813.79,530.79
  Layer 4 - Signal w8: v1(434.02,423.61) 424.39,423.61 418,430 409,435 380,435 372,427 372,395 373,395 403,365 403,300 403,272 448,227 621,227 664.47,270.47 664.47,328.6 682,346.13 682,360 692,370 752,370 803,319 856,319 876,339 876,433.13 847,462.13 847,483.87 853,489.87 853,496 840,509 840,523 832,531 v1(815,531)
  Layer 6 - Bottom Layer w8: U4.D10@422.01,411.6 v1(434.02,423.61)
GND: C1.2 C2.2 C3.2 C4.2 C5.2 C6.2 C8.2 C9.2 C10.2 C11.2 C12.2 C13.2 C14.2 C15.2 C16.2 C17.2 C18.2 C19.2 C20.2 C23.2 C24.2 C25.2 C26.2 C27.2 C28.2 C29.2 C30.2 C31.2 C32.2 C33.2 C34.2 C35.2 C38.2 C39.1 C40.2 C41.2 C42.1 C43.2 C45.2 C46.1 C47.2 C48.2 C49.2 P1.2 P1.3 P1.4 P1.5 R8.1 R12.1 R15.1 R16.1 U1.2 U2.1 U2.4 U2.5 U2.9 U3.2 U4.A3 U4.B2 U4.B9 U4.E10 U4.F2 U4.G3 U4.G6 U4.H8 U5.7 U5.33 | length 1122
  Layer 1 - Top Layer w8: U5.7@605.51,530.79 650.79,530.79 v3(700,580)
  Layer 1 - Top Layer w10: U3.2@355.62,610 405,610 v2(419,624)
  Layer 1 - Top Layer w12: C35.2@841,531 C34.2@872,531 867,530 v2(898,530)
  Layer 1 - Top Layer w15: v2(720,305) R12.1@720,327.32 R12.1@720,330.32
  Layer 2 - GND w8: 431,798 461,798
  Layer 2 - GND w12: 576.65,325 v1(602.05,350.39) 627.44,325
  Layer 5 - PWR w8: 431,798 461,798
  Layer 3 - Signal w8: 431,798 461,798
  Layer 3 - Signal w12: 576.65,325 v1(602.05,350.39) 626.44,326 ; 627.44,325 626.44,326 ; 651.83,351.39 626.44,326
  Layer 4 - Signal w8: 431,798 461,798
  Layer 6 - Bottom Layer w8: v1(433.94,449.61) 433.94,450 U4.B9@445.94,462.01 ; v1(457.95,300.79) 457.95,301.18 U4.H8@469.96,313.19 ; v1(505.98,325.59) 505.98,325.98 U4.G6@517.99,337.99 ; U4.G3@590.04,337.99 602.05,350 v1(602.05,350.39) 614.06,362.4 U4.F2@614.06,362.8 ; U4.A3@590.04,486.81 590.04,486.42 v1(602.05,474.41) 602.05,474.02 U4.B2@614.06,462.01
  Layer 6 - Bottom Layer w12: v2(720,305) C29.2@720,377
  Layer 6 - Bottom Layer w15: 295,300 350,300 365,315 365,365 387.6,387.6 U4.E10@421.93,387.6
  Layer 6 - Bottom Layer w20: C12.2@495,699.53 v2(535,699.53) 553.11,681.42 553.11,612.79 C14.2@535,594.69
  other v2: 410,90 410,115 245,250 621,264 245,280 621,285 662,354 845,360 845,390 395,455 395,480 164,598 164,626 164,655 785,770 820,770 715,780 750,780
  other v3: 310,199.25 310,230.75 700,533.74 653.74,580 746.26,580 700,626.26
N_IMAGER_PWDN: U4.D3 U5.27 | length 616.1
  Layer 1 - Top Layer w8: U5.27@729.53,674.49 v1(729.53,695)
  Layer 3 - Signal w8: v1(577.64,400.39) 593.03,385 610,385 620,395 790,395 805,410 805,455 770,490 770,685 760,695 v1(729.53,695)
  Layer 6 - Bottom Layer w8: v1(577.64,400.39) 578.03,400.39 U4.D3@590.04,412.4
N_IMAGER_RESET: U4.F10 U5.28 | length 1256.4
  Layer 1 - Top Layer w8: U5.28@709.84,674.49 v1(709.84,695)
  Layer 3 - Signal w8: v1(475,280) 545,210 745,210 775,240 775,300 790,315 875,315 895,335 895,480 845,530 845,550 825,570 795,570 785,580 785,695 765,715 720,715 709.84,704.84 v1(709.84,695)
  Layer 6 - Bottom Layer w8: U4.F10@421.93,362.8 402.8,362.8 395,355 395,290 405,280 v1(475,280)
NetC1_1: C1.1 C2.1 L5.1 L6.1 L7.2 R1.1
NetC5_1: C5.1 L1.2 R2.2 U2.6 | length 277
  Layer 1 - Top Layer w8: U2.6@347.4,205.16 384.92,205.16 385,205.08 v2(409.92,205.08)
  Layer 3 - Signal w8: v2(336,355) 322,341 322,255 371.92,205.08 v2(409.92,205.08)
NetC21_1: C21.1 U4.D2 | length 258.8
  Layer 3 - Signal w10: v1(601.65,400.39) 616.26,415 v1(785,415)
  Layer 6 - Bottom Layer w8: v1(601.65,400.39) 602.05,400.39 U4.D2@614.06,412.4 ; C21.1@735,410 740,415 v1(785,415)
NetC21_2: C21.2 U4.D1 | length 56.9
  Layer 6 - Bottom Layer w8: U4.D1@638.07,412.4 C21.2@695,412.4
